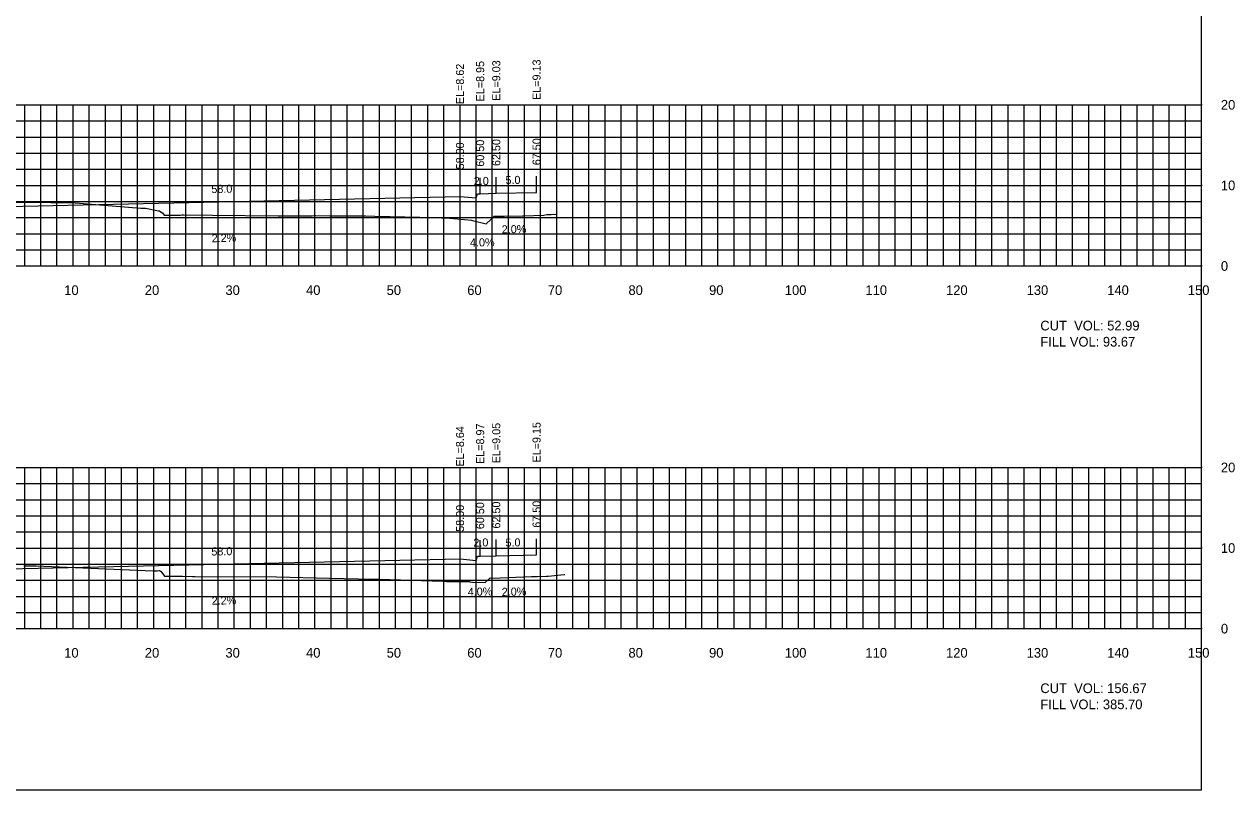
# Model space of a CAD drawing. Extents: x 1797419 to 1809236, y 248759 to 251512.
# Drawn here: x 1806714.9 to 1806865.1, y 250854.9 to 250949.9 of the extents above; entities that cross this region are included whole.
import ezdxf

# ---------------------------------------------------------------- set-up
doc = ezdxf.new("R2010")
doc.units = 0
for name, color, linetype in [('10', 7, 'Continuous'), ('3', 7, 'Continuous'), ('31', 7, 'Continuous'), ('4', 7, 'Continuous'), ('60', 7, 'Continuous'), ('ANNO-TXT', 7, 'Continuous'), ('CL-CNST', 7, 'Continuous'), ('Level 62', 7, 'Continuous'), ('M-ROADS', 7, 'Continuous')]:
    doc.layers.add(name, color=color, linetype=linetype)

msp = doc.modelspace()

# ---------------------------------------------------------------- linework, layer by layer
for p, q in [((1806769, 250928.51), (1806769, 250930.51)), ((1806771, 250928.34), (1806771, 250930.34)), ((1806771.5, 250928.84), (1806771.5, 250930.84)), ((1806773.5, 250928.92), (1806773.5, 250930.92)), ((1806778.5, 250929.02), (1806778.5, 250931.02)), ((1806769, 250883.53), (1806769, 250885.53)), ((1806771.5, 250883.86), (1806771.5, 250885.86)), ((1806773.5, 250883.94), (1806773.5, 250885.94)), ((1806778.5, 250884.04), (1806778.5, 250886.04))]:
    msp.add_line(p, q)
msp.add_lwpolyline([(1806561, 250854.89), (1806861, 250854.89), (1806861, 251044.89), (1806561, 251044.89)], close=True)
at = {"layer": '60'}
for p, q in [((1806861, 250919.89), (1806861, 250939.89)), ((1806861.06, 250939.89), (1806861, 250939.89)), ((1806861.06, 250929.89), (1806861, 250929.89)), ((1806561, 250919.89), (1806861, 250919.89)), ((1806721, 250919.83), (1806721, 250919.89)), ((1806731, 250919.83), (1806731, 250919.89)), ((1806741, 250919.83), (1806741, 250919.89)), ((1806751, 250919.83), (1806751, 250919.89)), ((1806761, 250919.83), (1806761, 250919.89)), ((1806771, 250919.83), (1806771, 250919.89)), ((1806781, 250919.83), (1806781, 250919.89)), ((1806791, 250919.83), (1806791, 250919.89)), ((1806801, 250919.83), (1806801, 250919.89)), ((1806811, 250919.83), (1806811, 250919.89)), ((1806821, 250919.83), (1806821, 250919.89)), ((1806831, 250919.83), (1806831, 250919.89)), ((1806841, 250919.83), (1806841, 250919.89)), ((1806851, 250919.83), (1806851, 250919.89)), ((1806861, 250919.83), (1806861, 250919.89)), ((1806861.06, 250919.89), (1806861, 250919.89)), ((1806861, 250874.89), (1806861, 250894.89)), ((1806861.06, 250894.89), (1806861, 250894.89)), ((1806861.06, 250884.89), (1806861, 250884.89)), ((1806561, 250874.89), (1806861, 250874.89)), ((1806721, 250874.83), (1806721, 250874.89)), ((1806731, 250874.83), (1806731, 250874.89)), ((1806741, 250874.83), (1806741, 250874.89)), ((1806751, 250874.83), (1806751, 250874.89)), ((1806761, 250874.83), (1806761, 250874.89)), ((1806771, 250874.83), (1806771, 250874.89)), ((1806781, 250874.83), (1806781, 250874.89)), ((1806791, 250874.83), (1806791, 250874.89)), ((1806801, 250874.83), (1806801, 250874.89)), ((1806811, 250874.83), (1806811, 250874.89)), ((1806821, 250874.83), (1806821, 250874.89)), ((1806831, 250874.83), (1806831, 250874.89)), ((1806841, 250874.83), (1806841, 250874.89)), ((1806851, 250874.83), (1806851, 250874.89)), ((1806861, 250874.83), (1806861, 250874.89)), ((1806861.06, 250874.89), (1806861, 250874.89))]:
    msp.add_line(p, q, dxfattribs=at)
at = {"layer": 'CL-CNST'}
for points in [[(1806642.27, 250926.43), (1806642.5, 250926.51), (1806643.5, 250926.47), (1806648.5, 250926.37), (1806650.5, 250926.29), (1806650.83, 250926.29), (1806651, 250925.79), (1806653, 250925.96), (1806711, 250927.23), (1806769, 250928.51), (1806771, 250928.34), (1806771.17, 250928.84), (1806771.5, 250928.84), (1806773.5, 250928.92), (1806778.5, 250929.02)], [(1806641.74, 250881.27), (1806642.5, 250881.53), (1806643.5, 250881.49), (1806648.5, 250881.39), (1806650.5, 250881.31), (1806650.83, 250881.31), (1806651, 250880.81), (1806653, 250880.97), (1806711, 250882.25), (1806769, 250883.53), (1806771, 250883.36), (1806771.17, 250883.86), (1806771.5, 250883.86), (1806773.5, 250883.94), (1806778.5, 250884.04)]]:
    msp.add_lwpolyline(points, dxfattribs=at)
at = {"layer": 'Level 62'}
for p, q in [((1806561, 250939.89), (1806861, 250939.89)), ((1806715, 250919.89), (1806715, 250939.89)), ((1806717, 250919.89), (1806717, 250939.89)), ((1806719, 250919.89), (1806719, 250939.89)), ((1806721, 250919.89), (1806721, 250939.89)), ((1806723, 250919.89), (1806723, 250939.89)), ((1806725, 250919.89), (1806725, 250939.89)), ((1806727, 250919.89), (1806727, 250939.89)), ((1806729, 250919.89), (1806729, 250939.89)), ((1806731, 250919.89), (1806731, 250939.89)), ((1806733, 250919.89), (1806733, 250939.89)), ((1806735, 250919.89), (1806735, 250939.89)), ((1806737, 250919.89), (1806737, 250939.89)), ((1806739, 250919.89), (1806739, 250939.89)), ((1806741, 250919.89), (1806741, 250939.89)), ((1806743, 250919.89), (1806743, 250939.89)), ((1806745, 250919.89), (1806745, 250939.89)), ((1806747, 250919.89), (1806747, 250939.89)), ((1806749, 250919.89), (1806749, 250939.89)), ((1806751, 250919.89), (1806751, 250939.89)), ((1806753, 250919.89), (1806753, 250939.89)), ((1806755, 250919.89), (1806755, 250939.89)), ((1806757, 250919.89), (1806757, 250939.89)), ((1806759, 250919.89), (1806759, 250939.89)), ((1806761, 250919.89), (1806761, 250939.89)), ((1806763, 250919.89), (1806763, 250939.89)), ((1806765, 250919.89), (1806765, 250939.89)), ((1806767, 250919.89), (1806767, 250939.89)), ((1806769, 250919.89), (1806769, 250939.89)), ((1806771, 250919.89), (1806771, 250939.89)), ((1806773, 250919.89), (1806773, 250939.89)), ((1806775, 250919.89), (1806775, 250939.89)), ((1806777, 250919.89), (1806777, 250939.89)), ((1806779, 250919.89), (1806779, 250939.89)), ((1806781, 250919.89), (1806781, 250939.89)), ((1806783, 250919.89), (1806783, 250939.89)), ((1806785, 250919.89), (1806785, 250939.89)), ((1806787, 250919.89), (1806787, 250939.89)), ((1806789, 250919.89), (1806789, 250939.89)), ((1806791, 250919.89), (1806791, 250939.89)), ((1806793, 250919.89), (1806793, 250939.89)), ((1806795, 250919.89), (1806795, 250939.89)), ((1806797, 250919.89), (1806797, 250939.89)), ((1806799, 250919.89), (1806799, 250939.89)), ((1806801, 250919.89), (1806801, 250939.89)), ((1806803, 250919.89), (1806803, 250939.89)), ((1806805, 250919.89), (1806805, 250939.89)), ((1806807, 250919.89), (1806807, 250939.89)), ((1806809, 250919.89), (1806809, 250939.89)), ((1806811, 250919.89), (1806811, 250939.89)), ((1806813, 250919.89), (1806813, 250939.89)), ((1806815, 250919.89), (1806815, 250939.89)), ((1806817, 250919.89), (1806817, 250939.89)), ((1806819, 250919.89), (1806819, 250939.89)), ((1806821, 250919.89), (1806821, 250939.89)), ((1806823, 250919.89), (1806823, 250939.89)), ((1806825, 250919.89), (1806825, 250939.89)), ((1806827, 250919.89), (1806827, 250939.89)), ((1806829, 250919.89), (1806829, 250939.89)), ((1806831, 250919.89), (1806831, 250939.89)), ((1806833, 250919.89), (1806833, 250939.89)), ((1806835, 250919.89), (1806835, 250939.89)), ((1806837, 250919.89), (1806837, 250939.89)), ((1806839, 250919.89), (1806839, 250939.89)), ((1806841, 250919.89), (1806841, 250939.89)), ((1806843, 250919.89), (1806843, 250939.89)), ((1806845, 250919.89), (1806845, 250939.89)), ((1806847, 250919.89), (1806847, 250939.89)), ((1806849, 250919.89), (1806849, 250939.89)), ((1806851, 250919.89), (1806851, 250939.89)), ((1806853, 250919.89), (1806853, 250939.89)), ((1806855, 250919.89), (1806855, 250939.89)), ((1806857, 250919.89), (1806857, 250939.89)), ((1806859, 250919.89), (1806859, 250939.89)), ((1806861, 250919.89), (1806861, 250939.89)), ((1806561, 250937.89), (1806861, 250937.89)), ((1806561, 250935.89), (1806861, 250935.89)), ((1806561, 250933.89), (1806861, 250933.89)), ((1806561, 250931.89), (1806861, 250931.89)), ((1806561, 250929.89), (1806861, 250929.89)), ((1806561, 250927.89), (1806861, 250927.89)), ((1806561, 250925.89), (1806861, 250925.89)), ((1806561, 250923.89), (1806861, 250923.89)), ((1806561, 250921.89), (1806861, 250921.89)), ((1806561, 250919.89), (1806861, 250919.89)), ((1806561, 250894.89), (1806861, 250894.89)), ((1806715, 250874.89), (1806715, 250894.89)), ((1806717, 250874.89), (1806717, 250894.89)), ((1806719, 250874.89), (1806719, 250894.89)), ((1806721, 250874.89), (1806721, 250894.89)), ((1806723, 250874.89), (1806723, 250894.89)), ((1806725, 250874.89), (1806725, 250894.89)), ((1806727, 250874.89), (1806727, 250894.89)), ((1806729, 250874.89), (1806729, 250894.89)), ((1806731, 250874.89), (1806731, 250894.89)), ((1806733, 250874.89), (1806733, 250894.89)), ((1806735, 250874.89), (1806735, 250894.89)), ((1806737, 250874.89), (1806737, 250894.89)), ((1806739, 250874.89), (1806739, 250894.89)), ((1806741, 250874.89), (1806741, 250894.89)), ((1806743, 250874.89), (1806743, 250894.89)), ((1806745, 250874.89), (1806745, 250894.89)), ((1806747, 250874.89), (1806747, 250894.89)), ((1806749, 250874.89), (1806749, 250894.89)), ((1806751, 250874.89), (1806751, 250894.89)), ((1806753, 250874.89), (1806753, 250894.89)), ((1806755, 250874.89), (1806755, 250894.89)), ((1806757, 250874.89), (1806757, 250894.89)), ((1806759, 250874.89), (1806759, 250894.89)), ((1806761, 250874.89), (1806761, 250894.89)), ((1806763, 250874.89), (1806763, 250894.89)), ((1806765, 250874.89), (1806765, 250894.89)), ((1806767, 250874.89), (1806767, 250894.89)), ((1806769, 250874.89), (1806769, 250894.89)), ((1806771, 250874.89), (1806771, 250894.89)), ((1806773, 250874.89), (1806773, 250894.89)), ((1806775, 250874.89), (1806775, 250894.89)), ((1806777, 250874.89), (1806777, 250894.89)), ((1806779, 250874.89), (1806779, 250894.89)), ((1806781, 250874.89), (1806781, 250894.89)), ((1806783, 250874.89), (1806783, 250894.89)), ((1806785, 250874.89), (1806785, 250894.89)), ((1806787, 250874.89), (1806787, 250894.89)), ((1806789, 250874.89), (1806789, 250894.89)), ((1806791, 250874.89), (1806791, 250894.89)), ((1806793, 250874.89), (1806793, 250894.89)), ((1806795, 250874.89), (1806795, 250894.89)), ((1806797, 250874.89), (1806797, 250894.89)), ((1806799, 250874.89), (1806799, 250894.89)), ((1806801, 250874.89), (1806801, 250894.89)), ((1806803, 250874.89), (1806803, 250894.89)), ((1806805, 250874.89), (1806805, 250894.89)), ((1806807, 250874.89), (1806807, 250894.89)), ((1806809, 250874.89), (1806809, 250894.89)), ((1806811, 250874.89), (1806811, 250894.89)), ((1806813, 250874.89), (1806813, 250894.89)), ((1806815, 250874.89), (1806815, 250894.89)), ((1806817, 250874.89), (1806817, 250894.89)), ((1806819, 250874.89), (1806819, 250894.89)), ((1806821, 250874.89), (1806821, 250894.89)), ((1806823, 250874.89), (1806823, 250894.89)), ((1806825, 250874.89), (1806825, 250894.89)), ((1806827, 250874.89), (1806827, 250894.89)), ((1806829, 250874.89), (1806829, 250894.89)), ((1806831, 250874.89), (1806831, 250894.89)), ((1806833, 250874.89), (1806833, 250894.89)), ((1806835, 250874.89), (1806835, 250894.89)), ((1806837, 250874.89), (1806837, 250894.89)), ((1806839, 250874.89), (1806839, 250894.89)), ((1806841, 250874.89), (1806841, 250894.89)), ((1806843, 250874.89), (1806843, 250894.89)), ((1806845, 250874.89), (1806845, 250894.89)), ((1806847, 250874.89), (1806847, 250894.89)), ((1806849, 250874.89), (1806849, 250894.89)), ((1806851, 250874.89), (1806851, 250894.89)), ((1806853, 250874.89), (1806853, 250894.89)), ((1806855, 250874.89), (1806855, 250894.89)), ((1806857, 250874.89), (1806857, 250894.89)), ((1806859, 250874.89), (1806859, 250894.89)), ((1806861, 250874.89), (1806861, 250894.89)), ((1806561, 250892.89), (1806861, 250892.89)), ((1806561, 250890.89), (1806861, 250890.89)), ((1806561, 250888.89), (1806861, 250888.89)), ((1806561, 250886.89), (1806861, 250886.89)), ((1806561, 250884.89), (1806861, 250884.89)), ((1806561, 250882.89), (1806861, 250882.89)), ((1806561, 250880.89), (1806861, 250880.89)), ((1806561, 250878.89), (1806861, 250878.89)), ((1806561, 250876.89), (1806861, 250876.89)), ((1806561, 250874.89), (1806861, 250874.89))]:
    msp.add_line(p, q, dxfattribs=at)
at = {"layer": 'M-ROADS'}
for points in [[(1806708.53, 250927.79), (1806718.22, 250927.78), (1806720.26, 250927.77), (1806720.36, 250927.77), (1806720.75, 250927.77), (1806729.41, 250927.06), (1806729.5, 250927.05), (1806729.53, 250927.05), (1806729.62, 250927.05), (1806729.91, 250927.06), (1806730, 250927.05), (1806730, 250927.05), (1806731.6, 250926.72), (1806731.72, 250926.74), (1806732.04, 250926.48), (1806732.08, 250926.48), (1806732.3, 250926.18), (1806733.93, 250926.19), (1806734.04, 250926.2), (1806734.16, 250926.2), (1806734.31, 250926.21), (1806734.47, 250926.22), (1806734.66, 250926.23), (1806734.68, 250926.23), (1806738.29, 250926.2), (1806746.44, 250926.12), (1806748.4, 250926.13), (1806749.73, 250926.13), (1806750.12, 250926.13), (1806750.64, 250926.13), (1806751.08, 250926.14), (1806751.1, 250926.14), (1806752.85, 250926.12), (1806753.1, 250926.12), (1806753.51, 250926.12), (1806756.68, 250926.1), (1806757.27, 250926.1), (1806758.44, 250926.09), (1806765.87, 250925.89), (1806766.71, 250925.87), (1806766.96, 250925.87), (1806766.98, 250925.87), (1806767.23, 250925.87), (1806768.69, 250925.73), (1806770.44, 250925.57), (1806770.55, 250925.55), (1806772.26, 250925.12), (1806772.82, 250925.64), (1806773.25, 250926.08), (1806773.51, 250926.08), (1806773.73, 250926.08), (1806774.46, 250926.07), (1806776.75, 250926.1), (1806776.89, 250926.1), (1806779.4, 250926.21), (1806779.77, 250926.28), (1806779.85, 250926.26), (1806779.95, 250926.26), (1806780.32, 250926.26), (1806780.88, 250926.31), (1806780.91, 250926.31)], [(1806714.87, 250882.67), (1806715.31, 250882.67), (1806716.41, 250882.66), (1806729.93, 250882.09), (1806730.98, 250882.05), (1806731.06, 250882.05), (1806731.35, 250882.05), (1806731.49, 250882.05), (1806731.49, 250882.05), (1806731.7, 250882.09), (1806731.8, 250882), (1806731.89, 250882), (1806732.32, 250881.4), (1806733.57, 250881.41), (1806733.66, 250881.41), (1806733.75, 250881.4), (1806733.86, 250881.4), (1806733.98, 250881.4), (1806734.14, 250881.39), (1806734.32, 250881.39), (1806734.55, 250881.38), (1806734.57, 250881.38), (1806735.83, 250881.37), (1806736.13, 250881.37), (1806746.24, 250881.31), (1806752.83, 250881.17), (1806758.24, 250881.04), (1806758.91, 250881.02), (1806759.01, 250881.01), (1806760.29, 250880.97), (1806760.3, 250880.97), (1806766.86, 250880.76), (1806767.34, 250880.75), (1806770.17, 250880.72), (1806770.24, 250880.71), (1806770.24, 250880.71), (1806770.54, 250880.66), (1806772.13, 250880.62), (1806772.49, 250880.96), (1806772.76, 250881.18), (1806772.91, 250881.15), (1806772.97, 250881.15), (1806777.88, 250881.35), (1806778.44, 250881.35), (1806778.6, 250881.35), (1806779.73, 250881.4), (1806779.81, 250881.41), (1806779.83, 250881.41), (1806779.85, 250881.41), (1806779.94, 250881.41), (1806781.94, 250881.59), (1806782.02, 250881.59)]]:
    msp.add_lwpolyline(points, dxfattribs=at)

# ---------------------------------------------------------------- texts
at = {"layer": '10'}
for s, p in [('10', (1806719.9, 250916.29)), ('20', (1806729.9, 250916.29)), ('30', (1806739.9, 250916.29)), ('40', (1806749.9, 250916.29)), ('50', (1806759.9, 250916.29)), ('60', (1806769.9, 250916.29)), ('70', (1806779.9, 250916.29)), ('80', (1806789.9, 250916.29)), ('90', (1806799.9, 250916.29)), ('100', (1806809.3, 250916.29)), ('110', (1806819.3, 250916.29)), ('120', (1806829.3, 250916.29)), ('130', (1806839.3, 250916.29)), ('140', (1806849.3, 250916.29)), ('150', (1806859.3, 250916.29)), ('10', (1806719.9, 250871.29)), ('20', (1806729.9, 250871.29)), ('30', (1806739.9, 250871.29)), ('40', (1806749.9, 250871.29)), ('50', (1806759.9, 250871.29)), ('60', (1806769.9, 250871.29)), ('70', (1806779.9, 250871.29)), ('80', (1806789.9, 250871.29)), ('90', (1806799.9, 250871.29)), ('100', (1806809.3, 250871.29)), ('110', (1806819.3, 250871.29)), ('120', (1806829.3, 250871.29)), ('130', (1806839.3, 250871.29)), ('140', (1806849.3, 250871.29)), ('150', (1806859.3, 250871.29))]:
    msp.add_text(s, height=1.2, dxfattribs=at).set_placement(p)
at = {"layer": '3'}
for s, p in [('EL=8.95', (1806772, 250940.31)), ('EL=9.03', (1806774, 250940.39)), ('EL=9.13', (1806779, 250940.49)), ('EL=8.62', (1806769.5, 250939.97)), ('58.00', (1806769.5, 250931.88)), ('60.50', (1806772, 250932.21)), ('62.50', (1806774, 250932.29)), ('67.50', (1806779, 250932.39)), ('EL=8.64', (1806769.5, 250894.99)), ('EL=8.97', (1806772, 250895.32)), ('EL=9.05', (1806774, 250895.4)), ('EL=9.15', (1806779, 250895.5)), ('58.00', (1806769.5, 250886.9)), ('60.50', (1806772, 250887.23)), ('62.50', (1806774, 250887.31)), ('67.50', (1806779, 250887.41))]:
    msp.add_text(s, height=1, rotation=90, dxfattribs=at).set_placement(p)
at = {"layer": '31'}
for s, p in [('20', (1806863.4, 250939.29)), ('10', (1806863.4, 250929.29)), ('0', (1806863.4, 250919.29)), ('20', (1806863.4, 250894.29)), ('10', (1806863.4, 250884.29)), ('0', (1806863.4, 250874.29))]:
    msp.add_text(s, height=1.2, dxfattribs=at).set_placement(p)
at = {"layer": '4'}
for s, rotation, p in [('58.0', 1.2603, (1806738.16, 250928.93)), ('5.0', 1.1458, (1806774.65, 250930.04)), ('2.0%', 1.1458, (1806774.19, 250923.93)), ('2.2%', 1.2603, (1806738.2, 250922.83)), ('4.0%', 1.1458, (1806770.25, 250922.29)), ('58.0', 1.2603, (1806738.16, 250883.95)), ('2.0', 1.1458, (1806770.67, 250885.06)), ('5.0', 1.1458, (1806774.65, 250885.06)), ('2.2%', 1.2603, (1806738.2, 250877.85)), ('4.0%', 1.1458, (1806769.97, 250878.95)), ('2.0%', 1.1458, (1806774.19, 250878.95))]:
    msp.add_text(s, height=1, rotation=rotation, dxfattribs=at).set_placement(p)
msp.add_text('2.0', height=1, dxfattribs=at).set_placement((1806770.71, 250929.94))
at = {"layer": 'ANNO-TXT'}
for s, p in [('CUT  VOL: 52.99', (1806841, 250911.89)), ('FILL VOL: 93.67', (1806841, 250909.89)), ('CUT  VOL: 156.67', (1806841, 250866.89)), ('FILL VOL: 385.70', (1806841, 250864.89))]:
    msp.add_text(s, height=1.2, dxfattribs=at).set_placement(p)

doc.saveas('drawing.dxf')
